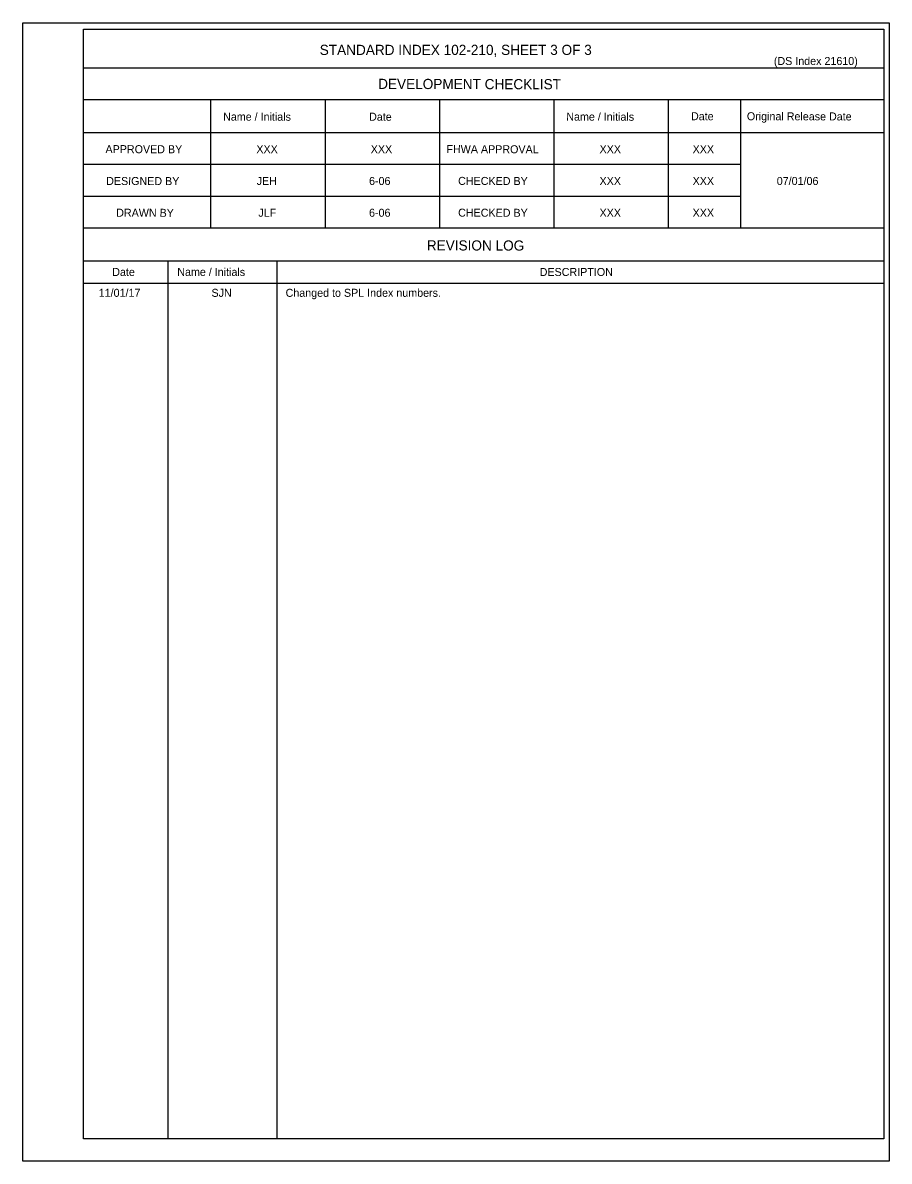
# Model space of a CAD drawing. Extents: x 10601.8 to 10619.6, y 76459.2 to 76469.
# Drawn here: x 10614.14 to 10619.6, y 76460.59 to 76467.76 of the extents above; entities that cross this region are included whole.
import ezdxf

# ---------------------------------------------------------------- set-up
doc = ezdxf.new("R2010")
doc.units = 0
for name, color, linetype in [('Border', 7, 'Continuous'), ('PlotBorder_dp', 7, 'Continuous'), ('TextStructures', 7, 'Continuous')]:
    doc.layers.add(name, color=color, linetype=linetype)

msp = doc.modelspace()

# ---------------------------------------------------------------- linework, layer by layer
at = {"layer": 'Border'}
for p, q in [((10619.5637, 76467.4758), (10614.5269, 76467.4758)), ((10619.5637, 76467.2758), (10614.5269, 76467.2758)), ((10615.3269, 76467.2758), (10615.3269, 76466.4688)), ((10616.0469, 76467.2758), (10616.0469, 76466.4688)), ((10616.7669, 76467.2758), (10616.7669, 76466.4688)), ((10617.4869, 76467.2758), (10617.4869, 76466.4688)), ((10618.2069, 76467.2758), (10618.2069, 76466.4688)), ((10618.6607, 76467.2758), (10618.6607, 76466.4688)), ((10619.5637, 76467.0688), (10614.5269, 76467.0688)), ((10618.6607, 76466.8688), (10614.5269, 76466.8688)), ((10618.6607, 76466.6688), (10614.5269, 76466.6688)), ((10619.5637, 76466.4688), (10614.5269, 76466.4688)), ((10619.5637, 76466.2619), (10614.5269, 76466.2619)), ((10615.057, 76466.2619), (10615.057, 76460.7353)), ((10615.7426, 76466.2619), (10615.7426, 76460.7353)), ((10619.5637, 76466.1209), (10614.5269, 76466.1209))]:
    msp.add_line(p, q, dxfattribs=at)
msp.add_lwpolyline([(10614.527, 76467.7209), (10619.5637, 76467.7209), (10619.5637, 76460.7353), (10614.527, 76460.7353)], close=True, dxfattribs=at)
at = {"layer": 'PlotBorder_dp'}
msp.add_line((10614.1443, 76460.5949), (10614.1443, 76460.5949), dxfattribs=at)
msp.add_lwpolyline([(10614.1443, 76467.7616), (10619.5977, 76467.7616), (10619.5977, 76460.5949), (10614.1443, 76460.5949)], close=True, dxfattribs=at)

# ---------------------------------------------------------------- texts
at = {"layer": 'TextStructures'}
for s, height, p in [('STANDARD INDEX 102-210, SHEET 3 OF 3', 0.064, (10616.0133, 76467.5589)), ('(DS Index 21610)', 0.0504, (10618.8716, 76467.4958)), ('XXX', 0.0504, (10615.6145, 76466.9405)), ('XXX', 0.0504, (10616.3345, 76466.9405)), ('XXX', 0.0504, (10617.7745, 76466.9405)), ('XXX', 0.0504, (10618.3603, 76466.9405)), ('JEH', 0.0504, (10615.6163, 76466.7405)), ('6-06', 0.0504, (10616.3237, 76466.7405)), ('XXX', 0.0504, (10617.7745, 76466.7405)), ('XXX', 0.0504, (10618.3603, 76466.7405)), ('07/01/06', 0.0504, (10618.8898, 76466.7405)), ('JLF', 0.0504, (10615.6269, 76466.5405)), ('6-06', 0.0504, (10616.3237, 76466.5405)), ('XXX', 0.0504, (10617.7745, 76466.5405)), ('XXX', 0.0504, (10618.3603, 76466.5405)), ('DESCRIPTION', 0.0504, (10617.3978, 76466.1676)), ('11/01/17', 0.0504, (10614.6223, 76466.0364)), ('SJN', 0.0504, (10615.3323, 76466.0364)), ('Changed to SPL Index numbers.', 0.0504, (10615.7985, 76466.0364))]:
    msp.add_text(s, height=height, dxfattribs=at).set_placement(p)
for s, height, p in [('DEVELOPMENT CHECKLIST', 0.064, (10616.3809, 76467.345)), ('Name / Initials', 0.0504, (10615.4051, 76467.1456)), ('Date', 0.0504, (10616.3238, 76467.1451)), ('Name / Initials', 0.0504, (10617.5651, 76467.1456)), ('Date', 0.0504, (10618.35, 76467.1481)), ('Original Release Date', 0.0504, (10618.7016, 76467.148)), ('APPROVED BY', 0.0504, (10614.6649, 76466.941)), ('FHWA APPROVAL', 0.0504, (10616.8107, 76466.941)), ('DESIGNED BY', 0.0504, (10614.6691, 76466.7406)), ('CHECKED BY', 0.0504, (10616.8844, 76466.741)), ('DRAWN BY', 0.0504, (10614.7323, 76466.5406)), ('CHECKED BY', 0.0504, (10616.8844, 76466.541)), ('REVISION LOG', 0.064, (10616.6872, 76466.3286)), ('Date', 0.0504, (10614.7075, 76466.1678)), ('Name / Initials', 0.0504, (10615.1167, 76466.1682))]:
    msp.add_text(s, height=height, rotation=359.87563, dxfattribs=at).set_placement(p)

doc.saveas('drawing.dxf')
